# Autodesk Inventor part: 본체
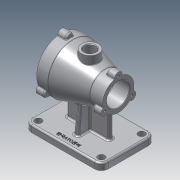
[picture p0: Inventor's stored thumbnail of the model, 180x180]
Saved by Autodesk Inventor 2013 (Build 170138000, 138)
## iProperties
Created: 2020-03
Part Number: 본체
Material: 알루미늄 6061
Document SubType Name: Modeling
Designer: user
Density: 2.71 g/cm^3
Mass: 998.506 g
Surface Area: 864.159 cm^2
Volume: 368.452 cm^3
Author: user
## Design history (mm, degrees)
sketch "스케치1"
  geometry: L1 (-50, 0)-(50, 0); L2 (-50, 0)-(-50, 44); L3 (-50, 44)-(-30, 44); L4 (-30, 44)-(27, 27.5); L5 (27, 27.5)-(50, 27.5); L6 (50, 27.5)-(50, 0); 2 further points
  constraints: 12 end point, 3 perpendicular, 1 coincident, 1 horizontal, 1 midpoint, 1 parallel
  dimensions: "d0" = 100 distance of L1.start L1.end; "d2" = 20 distance of L2.end L3.end; "d3" = 77 distance from line of L4.end L2; "d4" = 88 diameter of L3 L1; "d5" = 55 diameter of L5 L1
revolve "회전1" sketch "스케치1" stored, may be unused: angle "d6" = 90 deg
node "작업 평면1"
sketch "스케치2"
  geometry: L1 (-67.5, 47.5)-(67.5, 47.5); L2 (67.5, 47.5)-(67.5, -47.5); L3 (67.5, -47.5)-(-67.5, -47.5); L4 (-67.5, -47.5)-(-67.5, 47.5); L5 (-67.5, 47.5)-(67.5, -47.5); L6 (67.5, 47.5)-(-67.5, -47.5); 1 further point
  constraints: 12 end point, 2 midpoint, 2 parallel, 1 horizontal, 1 perpendicular
  dimensions: "d8" = 135 distance of L1.start L1.end; "d10" = 95 distance of L1.end L2.end
extrude "돌출1" join sketch "스케치2" distance "d11" = 12; taper "d12" = 0 deg
fillet "모깎기1" dims "d13" = 12
sketch "스케치3"
  geometry: C1 r 6 at (-55.5, 35.5); A1 r 12 centre (-55.5, 35.5) between (-55.5, 47.5) and (-67.5, 35.5) reference; 1 further point
  constraints: 1 centre point, 1 coincident
  dimensions: "d14" = 12 diameter of C1
extrude "돌출2" cut sketch "스케치3" distance "d16" = 12; taper "d17" = 0 deg
sketch "스케치4"
  geometry: L1 (-50, -44)-(-50, 44) reference; L2 (-50, 44)-(-30, 44) reference; L3 (-30, 44)-(27, 27.5) reference; L4 (27, 27.5)-(50, 27.5) reference; L5 (50, 27.5)-(50, -27.5) reference; L6 (50, -27.5)-(27, -27.5) reference; L7 (27, -27.5)-(-30, -44) reference; L8 (-30, -44)-(-50, -44) reference; L9 (-67.5, -75)-(67.5, -75) reference; L10 (67.5, -75)-(67.5, -87) reference; L11 (67.5, -87)-(-67.5, -87) reference; L12 (-67.5, -87)-(-67.5, -75) reference; L13 (-37, -75)-(-37, 0); L14 (-37, 0)-(37, 0); L15 (37, 0)-(37, -75); L16 (-37, -75)-(37, -75); 2 further points
  constraints: 8 end point, 2 perpendicular, 2 point on line, 1 coincident, 1 collinear, 1 midpoint, 1 parallel
  dimensions: "d18" = 37 distance from line of point (0, 0) L13; "d19" = 37 distance from line of L15 point (0, 0) (derived)
extrude "돌출3" join sketch "스케치4" stored distance "d20" = 8; taper "d21" = 0 deg
sketch "스케치5"
  geometry: L1 (0, 18.438)-(0, -18.438); L2 (0, 18.438)-(-75, 25); L3 (-75, 25)-(-75, -25); L4 (-75, -25)-(0, -18.438); L5 (-75, 4)-(-75, -4) reference; L6 (-75, -29.5)-(-75, -41.5) reference; 3 further points
  constraints: 8 end point, 3 midpoint, 1 coincident, 1 parallel, 1 vertical
  dimensions: "d22" = 50 distance of L2.end L3.end; "d24" = 95 deg angle of L6 L4
extrude "돌출4" join sketch "스케치5" stored distance "d26" = 8; taper "d27" = 0 deg
node "작업 평면2"
sketch "스케치6"
  geometry: C1 r 15 at (0, 0); 1 further point
  constraints: 1 centre point, 1 coincident
  dimensions: "d29" = 30 diameter of C1
extrude "돌출5" join sketch "스케치6" stored distance "d31" = 8; taper "d32" = 0 deg
sketch "스케치7"
  geometry: C1 r 15 at (0, 0) reference; C2 r 10 at (0, 0)
  constraints: 1 centre point
  dimensions: "d33" = 20 diameter of C2
extrude "돌출6" cut sketch "스케치7" distance "d35" = 25; taper "d36" = 0 deg
sketch "스케치8"
  geometry: L1 (-50, 0)-(50, 0); L2 (-50, 0)-(-50, 36); L3 (-50, 36)-(-27, 36); L4 (-27, 36)-(-27, 26); L5 (-27, 26)-(20, 26); L6 (20, 26)-(20, 20); L7 (20, 20)-(50, 20); L8 (50, 20)-(50, 0); 2 further points
  constraints: 16 end point, 4 perpendicular, 3 parallel, 1 coincident, 1 horizontal, 1 midpoint
  dimensions: "d37" = 100 distance of L1.start L1.end; "d39" = 72 diameter of L3 L1; "d40" = 52 diameter of L5 L1; "d41" = 40 diameter of L7 L1; "d42" = 30 distance of L6.end L7.end; "d43" = 47 distance of L4.end L5.end; "d44" = 23 distance of L2.end L3.end (derived)
revolve "회전2" sketch "스케치8" stored, may be unused: angle "d45" = 90 deg
sketch "스케치9"
  geometry: C1 r 36 at (0, 0) reference; C2 r 44 at (0, 0); C3 r 7 at (0, 44); 1 further point
  constraints: 2 centre point, 2 vertical alignment, 1 coincident, 1 other
  dimensions: "d46" = 88 diameter of C2; "d48" = 14 diameter of C3
extrude "돌출7" join sketch "스케치9" distance "d49" = 15; taper "d50" = 0 deg
sketch "스케치10"
  geometry: A1 r 7 centre (0, 0) between (6.978, -0.557) and (-6.978, -0.557) reference; 1 further point
  constraints: 1 coincident
hole "구멍1" sketch "스케치10" at (0, 0) diameter "d51" = 4.134; stored, may be unused: countersink angle "d55" = 90 deg, drill point angle "d57" = 118 deg; dims "d52" = 9, "d53" = 4, "d54" = 2, "d56" = 11
fillet "모깎기2" dims "d58" = 3
fillet "모깎기3" dims "d59" = 1
fillet "모깎기4" dims "d63" = 3
fillet "모깎기5" dims "d64" = 3
sketch "스케치11"
  geometry: C1 r 20 at (0, 0) reference; C2 r 7 at (0, 27.5); 1 further point
  constraints: 2 vertical alignment, 1 centre point, 1 other
  dimensions: "d65" = 14 diameter of C2
extrude "돌출8" join sketch "스케치11" distance "d67" = 15; taper "d68" = 0 deg
sketch "스케치12"
  geometry: A1 r 7 centre (0, 0) between (6.943, -0.891) and (-6.943, -0.891) reference; 1 further point
  constraints: 1 coincident
hole "구멍2" sketch "스케치12" at (0, 0) diameter "d69" = 4.134; stored, may be unused: countersink angle "d73" = 90 deg, drill point angle "d75" = 118 deg; dims "d70" = 9, "d71" = 4, "d72" = 2, "d74" = 11
fillet "모깎기6" dims "d76" = 3
fillet "모깎기7" dims "d77" = 1
fillet "모깎기8" dims "d81" = 3
fillet "모깎기9" dims "d82" = 3
fillet "모깎기10" dims "d83" = 3
node "작업 평면3"
sketch "스케치13"
  geometry: L1 (55.5, 47.5)-(-55.5, 47.5) reference; 2 further points
  constraints: 1 vertical alignment, 1 other
  dimensions: "d85" = 10 distance from line of L1 point (0, 37.5)
feature "엠보싱1" sketch "스케치13" dims "d0" = 100, "d2" = 20, "d3" = 77, "d4" = 88, "d5" = 55, "d86" = 0.5, "d87" = 0
chamfer "모따기1" distance "d88" = 1; stored, may be unused: second distance "d89" = 2, angle "d90" = 45 deg
fillet "모깎기11" dims "d91" = 3
chamfer "모따기2" distance "d92" = 1; stored, may be unused: second distance "d93" = 2, angle "d94" = 45 deg
fillet "모깎기12" dims "d95" = 1
node "솔리드1"
mirror "대칭1"
mirror "대칭2"
pattern_circular "원형 패턴1" dims "d61" = 360 deg
pattern_circular "원형 패턴2" dims "d79" = 360 deg
node "절단 모서리 투영1"
other parameters: "d7" = -87, "d28" = 45, "d84" = -54.75
